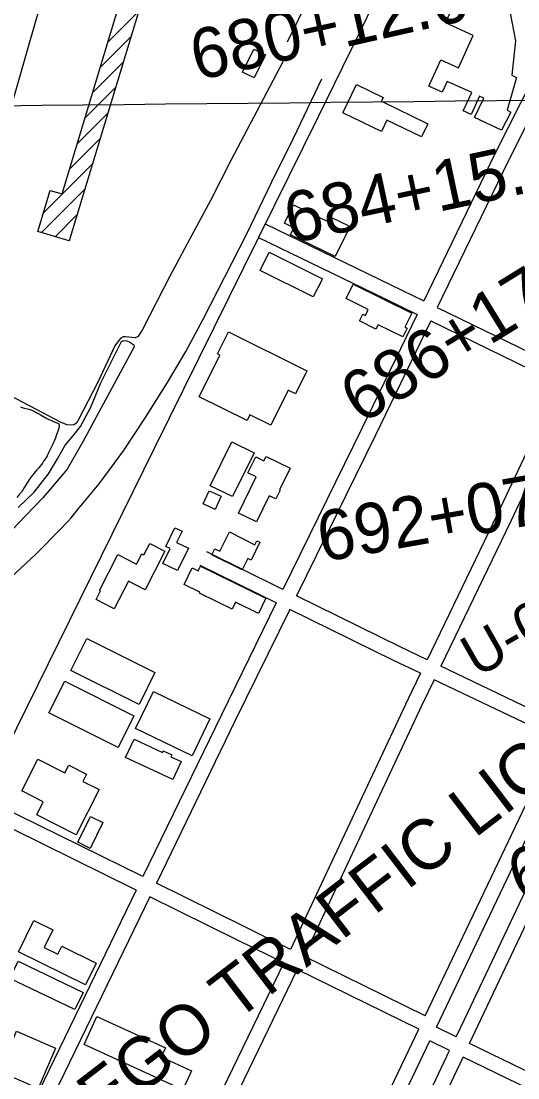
# Model space of a CAD drawing. Extents: x 3651524 to 3689615, y 505651 to 531377.
# Drawn here: x 3657229 to 3658220, y 515199 to 517307 of the extents above; entities that cross this region are included whole.
import ezdxf

# ---------------------------------------------------------------- set-up
doc = ezdxf.new("R2010")
doc.units = 0
for name, color, linetype in [('V-BLDG-OTLN', 7, 'Continuous'), ('V-CHAN-NAID', 7, 'Continuous'), ('V-GRID-MAJR', 7, 'Continuous'), ('V-RAIL-TRAK', 7, 'Continuous'), ('V-RIVR-RANG-IDEN', 7, 'Continuous'), ('V-ROAD-CNTR', 7, 'Continuous'), ('V-SITE-VEGE', 7, 'Continuous'), ('V-SURV-IDEN', 7, 'Continuous'), ('V-TOPO-SHOR', 7, 'Continuous')]:
    doc.layers.add(name, color=color, linetype=linetype)

msp = doc.modelspace()

# ---------------------------------------------------------------- linework, layer by layer
at = {"layer": 'V-BLDG-OTLN'}
for p, q in [((3657402.031, 517265.381), (3657463.228, 517326.578)), ((3657386.708, 517214.703), (3657447.906, 517275.9)), ((3657371.385, 517164.024), (3657432.584, 517225.223)), ((3657356.062, 517113.346), (3657417.262, 517174.546)), ((3657340.739, 517062.667), (3657401.94, 517123.868)), ((3657325.416, 517011.989), (3657386.618, 517073.191)), ((3657273.597, 516924.815), (3657371.296, 517022.513)), ((3657269.482, 516885.344), (3657355.974, 516971.836)), ((3657296.629, 516877.136), (3657340.652, 516921.158)), ((3657323.776, 516868.927), (3657325.33, 516870.481))]:
    msp.add_line(p, q, dxfattribs=at)
msp.add_lwpolyline([(3657498.904, 517444.574), (3657324.769, 516868.627), (3657262.319, 516887.51), (3657287.122, 516969.549), (3657310.451, 516962.495), (3657421.846, 517330.914)], dxfattribs=at)
for points in [[(3658078.818, 517186.981), (3658068.987, 517165.309), (3658042.351, 517177.388), (3658066.114, 517229.778), (3658101.456, 517213.746), (3658130.853, 517278.559), (3658075.508, 517303.662), (3658098.726, 517354.853), (3658134.396, 517338.674), (3658161.244, 517397.865), (3658190.962, 517384.386), (3658205.151, 517319.372), (3658215.458, 517267.819), (3658207.756, 517199.463), (3658217.115, 517194.575), (3658198.841, 517129.358), (3658205.863, 517125.69), (3658187.507, 517089.408), (3658133.63, 517114.568), (3658152.025, 517153.213), (3658143.833, 517157.492), (3658127.241, 517120.585), (3658110.838, 517127.962), (3658128.164, 517164.598)], [(3657716.625, 517240.026), (3657693.964, 517193.78), (3657670.598, 517205.235), (3657693.261, 517251.478)], [(3657947.744, 517087.149), (3657871.056, 517124.523), (3657898.282, 517180.39), (3657951.291, 517154.559), (3657947.869, 517147.536), (3658040.684, 517102.304), (3658027.97, 517076.217), (3657958.836, 517109.908)], [(3657855.766, 516837.639), (3657766.721, 516881.18), (3657773.322, 516894.678), (3657754.273, 516903.992), (3657772.269, 516940.793), (3657843.568, 516905.93), (3657848.358, 516915.731), (3657882.589, 516898.993), (3657877.577, 516888.745), (3657880.143, 516887.492)], [(3657811.963, 516756.948), (3657705.983, 516809.829), (3657724.059, 516846.054), (3657830.037, 516793.175)], [(3657891.354, 516782.233), (3658008.579, 516724.727), (3657994.895, 516696.831), (3657999.216, 516694.709), (3657990.692, 516677.334), (3657941.104, 516701.66), (3657936.828, 516692.942), (3657903.902, 516709.094), (3657910.525, 516722.595), (3657915.813, 516720), (3657921.634, 516731.866), (3657877.313, 516753.608)], [(3657642.704, 516687.195), (3657799.069, 516609.846), (3657776.273, 516563.764), (3657761.736, 516570.955), (3657727.141, 516501.022), (3657685.575, 516521.579), (3657680.154, 516510.621), (3657584.408, 516557.985), (3657625.479, 516641.011), (3657620.963, 516643.245)], [(3657693.687, 516446.195), (3657650.696, 516358.653), (3657606.389, 516380.411), (3657649.379, 516467.953)], [(3657765.658, 516415.794), (3657744.678, 516372.387), (3657745.862, 516371.815), (3657737.33, 516354.166), (3657724.057, 516360.582), (3657698.74, 516308.202), (3657662.828, 516325.559), (3657697.836, 516397.995), (3657681.506, 516405.89), (3657697.109, 516438.177), (3657713.454, 516430.276), (3657717.667, 516438.99)], [(3657616.072, 516333.344), (3657592.102, 516344.151), (3657603.813, 516370.126), (3657627.785, 516359.318)], [(3657562.756, 516256.001), (3657540.976, 516211.099), (3657511.808, 516225.248), (3657526.249, 516255.018), (3657517.432, 516259.296), (3657535.637, 516296.818), (3657550.114, 516289.793), (3657539.252, 516267.402)], [(3657644.373, 516288.302), (3657695.491, 516262.802), (3657699.387, 516270.607), (3657705.34, 516267.636), (3657687.689, 516232.248), (3657681.35, 516235.41), (3657669.947, 516212.549), (3657609.41, 516242.748), (3657615.435, 516254.825), (3657625.235, 516249.937)], [(3657515.538, 516250.027), (3657476.136, 516173.002), (3657442.865, 516190.023), (3657414.6, 516134.77), (3657378.453, 516153.261), (3657387.286, 516170.526), (3657385.006, 516171.693), (3657421.629, 516243.285), (3657459.044, 516224.144), (3657469.507, 516244.598), (3657473.726, 516242.439), (3657485.473, 516265.405)], [(3657587.017, 516220.145), (3657717.471, 516156.44), (3657702.465, 516125.713), (3657656.606, 516148.108), (3657649.733, 516134.03), (3657584.519, 516165.877), (3657585.69, 516168.277), (3657554.061, 516183.723), (3657570.051, 516216.47), (3657582.305, 516210.492)], [(3657359.765, 516075.683), (3657495.92, 516008.021), (3657464.219, 515944.23), (3657328.062, 516011.892)], [(3657422.303, 515858.378), (3657284.169, 515927.614), (3657315.796, 515990.713), (3657453.93, 515921.477)], [(3657570.054, 515841.981), (3657457.297, 515896.575), (3657492.858, 515970.024), (3657605.615, 515915.431)], [(3657531.758, 515794.519), (3657437.419, 515838.719), (3657454.309, 515874.768), (3657510.741, 515848.328), (3657512.269, 515851.589), (3657529.573, 515843.483), (3657527.848, 515839.798), (3657548.449, 515830.148)], [(3657384.476, 515774.479), (3657338.869, 515683.976), (3657259.949, 515723.744), (3657273.192, 515750.024), (3657230.227, 515771.674), (3657262.118, 515834.961), (3657316.14, 515807.737), (3657323.947, 515823.234), (3657359.66, 515805.238), (3657352.324, 515790.681)], [(3657392.195, 515708.749), (3657366.427, 515657.131), (3657341.775, 515669.435), (3657367.543, 515721.051)], [(3657357.467, 515385.145), (3657223.63, 515451.061), (3657254.288, 515513.313), (3657292.12, 515494.681), (3657274.796, 515459.504), (3657301.996, 515446.108), (3657309.987, 515462.334), (3657378.793, 515428.448)], [(3657335.971, 515335.602), (3657206.418, 515397.568), (3657222.827, 515431.874), (3657352.38, 515369.907)], [(3657551.585, 515175.671), (3657354.48, 515265.825), (3657380.175, 515322.001), (3657516.958, 515259.436), (3657508.578, 515241.115), (3657568.899, 515213.526)], [(3657219.76, 515292.521), (3657297.426, 515258.969), (3657262.587, 515178.324), (3657184.921, 515211.876)]]:
    msp.add_lwpolyline(points, close=True, dxfattribs=at)
at = {"layer": 'V-GRID-MAJR'}
msp.add_spline([(3655702.37, 517123.07), (3660982.023, 517177.978), (3666261.669, 517233.653), (3671541.307, 517290.097), (3676820.936, 517347.309), (3682100.557, 517405.288), (3687380.17, 517464.035)], degree=3, dxfattribs=at)
at = {"layer": 'V-RAIL-TRAK'}
msp.add_lwpolyline([(3657201.33, 516190.752), (3657257.281, 516243.572), (3657310.721, 516297.479), (3657316.775, 516303.601), (3657322.684, 516309.861), (3657328.443, 516316.259), (3657334.05, 516322.792), (3657339.504, 516329.455), (3657344.8, 516336.242), (3657384.441, 516384.38), (3657433.143, 516450.381), (3657475.934, 516514.262), (3657520.99, 516586.216), (3657557.63, 516648.494), (3657591.75, 516711.609), (3657679.605, 516883.054), (3657728.335, 516985.427), (3657772.345, 517073.944), (3657828.906, 517192.115)], dxfattribs=at)
at = {"layer": 'V-ROAD-CNTR'}
for points in [[(3658078.641, 517636.778), (3658016.474, 517514.148), (3657821.364, 517115.979)], [(3658278.416, 517248.37), (3658174.45, 517042.364), (3658032.287, 516749.182)], [(3658305.198, 517234.855), (3658201.34, 517029.06), (3658059.268, 516736.068)], [(3657821.364, 517115.979), (3657494.654, 516454.852), (3657091.838, 515639.148), (3656710.83, 514875.472), (3656430.01, 514305.598), (3656056.096, 513550.048), (3655742.777, 512921.615)], [(3657715.786, 516902.598), (3657966.946, 516780.941), (3658032.286, 516749.182)], [(3657702.708, 516875.598), (3657953.85, 516753.951), (3658019.197, 516722.189)], [(3658467.954, 516854.347), (3658408.248, 516738.45), (3658205.908, 516310.11), (3658066.086, 516020.436)], [(3658059.267, 516736.068), (3658315.182, 516611.676)], [(3658019.197, 516722.189), (3657908.783, 516494.483), (3657751.238, 516173.813)], [(3658046.179, 516709.074), (3657935.743, 516481.323), (3657778.157, 516160.571)], [(3658046.178, 516709.074), (3658302.368, 516584.548)], [(3658302.369, 516584.55), (3658178.836, 516323.038), (3658039.011, 516033.357)], [(3658096.848, 515281.202), (3658113.326, 515316.012), (3658308.977, 515728.143), (3658545.459, 516232.752), (3658625.562, 516398.014), (3658658.295, 516444.661), (3658689.779, 516480.667)], [(3657751.239, 516173.813), (3657599.717, 516248.35)], [(3657738.01, 516146.887), (3657586.475, 516221.431)], [(3657738.009, 516146.887), (3657628.408, 515923.801), (3657471.798, 515600.838)], [(3658039.011, 516033.356), (3657985.13, 516059.069), (3657778.162, 516160.581)], [(3657764.929, 516133.645), (3657655.368, 515910.641), (3657498.699, 515587.557)], [(3658025.971, 516006.338), (3657972.064, 516032.063), (3657764.934, 516133.655)], [(3658057.524, 515300.282), (3658130.981, 515454.113), (3658443.785, 516109.844)], [(3658311.931, 515903.116), (3658066.086, 516020.436)], [(3658025.97, 516006.34), (3658001.549, 515955.745), (3657787.846, 515500.383), (3657766.206, 515455.713)], [(3658053.045, 515993.419), (3658028.637, 515942.851), (3657814.926, 515487.469), (3657793.132, 515442.485)], [(3658299.015, 515876.038), (3658053.046, 515993.418)], [(3658035.36, 515323.487), (3658103.907, 515467.035), (3658299.014, 515876.038)], [(3658123.84, 515268.105), (3658140.434, 515303.162), (3658336.111, 515715.345), (3658385.307, 515820.32)], [(3657471.799, 515600.837), (3657222.975, 515723.684), (3657150.63, 515758.532)], [(3657458.71, 515573.843), (3657209.825, 515696.72), (3657137.61, 515731.505)], [(3657766.206, 515455.712), (3657673.809, 515501.104), (3657498.7, 515587.557)], [(3657458.709, 515573.845), (3657213.181, 515067.513), (3657071.929, 514772.098)], [(3657485.609, 515560.563), (3657240.21, 515054.497), (3657099.543, 514760.302)], [(3657753.126, 515428.713), (3657660.555, 515474.19), (3657485.61, 515560.562)], [(3657753.126, 515428.715), (3657559.14, 515028.303), (3657379.904, 514644.716)], [(3658035.36, 515323.487), (3657793.132, 515442.484)], [(3657780.052, 515415.486), (3657586.23, 515015.413), (3657407.038, 514631.92)], [(3658022.431, 515296.413), (3657780.052, 515415.485)], [(3658096.849, 515281.202), (3658057.524, 515300.283)], [(3657656.213, 514529.304), (3657725.7, 514675.015), (3658022.431, 515296.413)], [(3657818.427, 514799.58), (3658044.596, 515273.21)], [(3658084.013, 515254.085), (3658044.597, 515273.21)], [(3658363.915, 515151.619), (3658123.84, 515268.106)], [(3657902.507, 514870.649), (3658084.012, 515254.086)], [(3657929.623, 514857.813), (3658111.004, 515240.989)], [(3658350.891, 515124.593), (3658111.005, 515240.988)]]:
    msp.add_lwpolyline(points, dxfattribs=at)
at = {"layer": 'V-SITE-VEGE'}
for points in [[(3657223.032, 516337.11), (3657255.233, 516367.504), (3657283.524, 516404.141), (3657301.415, 516434.269), (3657316.487, 516461.071), (3657331.984, 516479.014), (3657347.52, 516498.31), (3657367.707, 516537.224), (3657388.169, 516585.661), (3657429.36, 516668.231), (3657432.819, 516670.174), (3657439.604, 516669.296), (3657445.668, 516667.08), (3657453.676, 516661.403), (3657454.239, 516657.3), (3657352.101, 516468.219), (3657320.558, 516413.289), (3657272.629, 516356.789), (3657237.53, 516320.349), (3657199.615, 516280.587)], [(3657227.448, 516537.826), (3657232.967, 516536.147), (3657244.004, 516533.048), (3657246.005, 516532.231), (3657248.272, 516531.916), (3657251.522, 516530.556), (3657255.253, 516528.424), (3657257.998, 516527.08), (3657261.477, 516524.957), (3657264.727, 516523.599), (3657266.966, 516522.27), (3657268.95, 516520.949), (3657272.184, 516519.085), (3657275.414, 516516.967), (3657278.164, 516515.876), (3657279.897, 516514.561), (3657281.904, 516513.998), (3657284.394, 516512.662), (3657291.399, 516509.93), (3657293.391, 516508.861), (3657298.134, 516506.701), (3657302.39, 516505.06), (3657304.129, 516503.999), (3657304.561, 516501.458), (3657304.727, 516498.417), (3657304.133, 516495.4), (3657302.738, 516490.886), (3657301.372, 516487.384), (3657298.331, 516478.365), (3657297.239, 516475.614), (3657296.41, 516473.109), (3657294.776, 516469.108), (3657293.44, 516466.617), (3657292.341, 516463.615), (3657290.196, 516459.376), (3657289.113, 516456.877), (3657284.294, 516447.657), (3657282.942, 516444.661), (3657280.528, 516439.924), (3657276.809, 516433.708), (3657273.644, 516429.245), (3657271.261, 516425.52), (3657263.908, 516416.122), (3657260.498, 516411.917), (3657255.01, 516405.753), (3657251.854, 516401.542), (3657245.56, 516393.883), (3657237.342, 516380.714), (3657235.738, 516377.724), (3657232.826, 516373.253), (3657231.228, 516370.519)], [(3657231.228, 516370.519), (3657229.381, 516367.789), (3657225.711, 516363.341), (3657223.104, 516360.633), (3657220.474, 516357.168)]]:
    msp.add_lwpolyline(points, dxfattribs=at)
at = {"layer": 'V-TOPO-SHOR'}
msp.add_line((3657843.052, 517434.435), (3657759.889, 517264.883), dxfattribs=at)
for points in [[(3657275.225, 517369.83), (3657243.199, 517255.785), (3657212.401, 517149.081), (3657189.494, 517069.11), (3657178.812, 517024.906), (3657176.369, 517010.732), (3657179.352, 516942.802)], [(3657750.884, 517225.848), (3657647.519, 517029.291), (3657606.723, 516949.259)], [(3657606.723, 516949.259), (3657564.821, 516871.351), (3657525.041, 516797.208), (3657471.145, 516692.186), (3657464.739, 516681.686), (3657461.305, 516677.207), (3657456.424, 516675.569), (3657449.832, 516676.267), (3657443.999, 516676.943), (3657436.899, 516677.656), (3657432.817, 516677.264), (3657427.654, 516674.616), (3657422.933, 516669.664), (3657415.772, 516659.443), (3657382.694, 516588.414), (3657342.289, 516510.217), (3657339.354, 516505.47), (3657333.909, 516501.812), (3657328.549, 516501.204), (3657320.693, 516502.191), (3657308.866, 516506.602), (3657168.035, 516580.097), (3657082.718, 516620.453), (3656916.096, 516699.268)]]:
    msp.add_lwpolyline(points, dxfattribs=at)

# ---------------------------------------------------------------- texts
at = {"layer": 'V-CHAN-NAID'}
msp.add_text('WESTWEGO TRAFFIC LIGHT (101.4)', height=100, rotation=37.493815, dxfattribs=at).set_placement((3656984.322, 514794.391))
at = {"layer": 'V-RIVR-RANG-IDEN'}
msp.add_text('U-070', height=83, rotation=29.758326, dxfattribs=at).set_placement((3658138.579, 515996.748))
at = {"layer": 'V-SURV-IDEN'}
for s, rotation, p in [('680+12.6', 12.681815, (3657579.695, 517188.274)), ('684+15.0', 12.100805, (3657766.407, 516863.218)), ('686+17.8', 31.644619, (3657907.025, 516501.762)), ('692+07.2', 10.005238, (3657829.513, 516228.105)), ('698+28.3', 19.075, (3658222.348, 515551.131))]:
    msp.add_text(s, height=100, rotation=rotation, dxfattribs=at).set_placement(p)

doc.saveas('drawing.dxf')
